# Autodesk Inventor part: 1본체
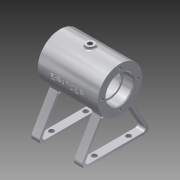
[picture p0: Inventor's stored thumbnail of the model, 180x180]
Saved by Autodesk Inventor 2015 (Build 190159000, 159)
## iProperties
Created: 2016-03
Part Number: 1본체
Material: 알루미늄 6061
Document SubType Name: Modeling
Designer: Administrator
Density: 2.7 g/cm^3
Appearance: 알루미늄 - 평지
Mass: 212.731 g
Surface Area: 333.697 cm^2
Volume: 78.7893 cm^3
Author: Administrator
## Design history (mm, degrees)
sketch "스케치1"
  geometry: C1 r 26 at (0, 0); 1 further point
  constraints: 1 centre point, 1 coincident
  dimensions: "d0" = 52 diameter of C1
extrude "돌출1" new body sketch "스케치1" distance "d1" = 70; taper "d2" = 0 deg
node "작업 평면2"
  node "작업 평면1"
sketch "스케치2"
  geometry: L1 (-33.934, -65)-(33.934, -65); L2 (16.613, -20)-(38.264, -57.5); L3 (-16.613, -20)-(-38.264, -57.5); L4 (14.183, -21.791)-(34.8, -57.5); L5 (-14.183, -21.791)-(-34.8, -57.5); L6 (-32.202, -62)-(32.202, -62); A1 r 26 centre (0, 0) between (16.613, -20) and (-16.613, -20) reference; A2 r 5 centre (-33.934, -60) between (-38.264, -57.5) and (-33.934, -65); A3 r 5 centre (33.934, -60) between (33.934, -65) and (38.264, -57.5); A4 r 3 centre (-32.202, -59) between (-34.8, -57.5) and (-32.202, -62); A5 r 3 centre (32.202, -59) between (32.202, -62) and (34.8, -57.5); 1 further point
  constraints: 12 end point, 12 point on circle, 8 tangent, 4 centre point, 2 equal radius, 2 horizontal
  dimensions: "d5" = 65 distance from line of point (0, 0) L1; "d8" = 5 radius of A2; "d10" = 3 distance between parallel lines of L4 L2; "d11" = 3 distance between parallel lines of L6 L1; "d46" = 3 radius of A4
extrude "돌출2" join sketch "스케치2" distance "d13" = 10; taper "d14" = 0 deg
node "작업 평면3"
sketch "스케치4"
  geometry: L1 (0, 10)-(67.868, 10) reference; L2 (33.934, 10)-(33.934, 37.245); L3 (0, -40)-(67.868, -40) reference; L4 (0, -50)-(67.868, -50) reference; C1 r 3 at (13.934, 5); C2 r 3 at (53.934, 5); C3 r 3 at (13.934, -45); C4 r 3 at (53.934, -45); 1 further point
  constraints: 4 centre point, 2 end point, 1 midpoint, 1 vertical
  dimensions: "d15" = 6 diameter of C1; "d16" = 20 distance from line of L2 C1.centre; "d17" = 5 distance from line of L1 C1.centre; "d18" = 6 diameter of C2; "d19" = 40 distance of C1.centre C2.centre; "d20" = 6 diameter of C3; "d21" = 6 diameter of C4; "d22" = 5 distance from line of L3 C4.centre; "d23" = 40 distance of C3.centre C4.centre; "d24" = 5 distance from line of L4 C3.centre; "d25" = 20 distance from line of C3.centre L2
extrude "돌출3" cut sketch "스케치4" stored distance "d26" = 10; taper "d27" = 0 deg
fillet "모깎기1" dims "d28" = 0.5
sketch "스케치5"
  geometry: L1 (0, 0)-(0, 70); L2 (16, 70)-(0, 70); L3 (0, 0)-(16, 0); L4 (16, 70)-(16, 58.3); L5 (14, 58)-(14, 56); L6 (21, 53)-(21, 17); L7 (16, 0)-(16, 11.7); L8 (14, 12)-(14, 14); L9 (14, 12)-(15.7, 12); L10 (14, 14)-(18, 14); L11 (14, 56)-(18, 56); L12 (14, 58)-(15.7, 58); A1 r 0.3 centre (15.7, 58.3) between (15.7, 58) and (16, 58.3); A2 r 0.3 centre (15.7, 11.7) between (16, 11.7) and (15.7, 12); A3 r 3 centre (18, 17) between (18, 14) and (21, 17); A4 r 3 centre (18, 53) between (21, 53) and (18, 56); 2 further points
  constraints: 24 end point, 8 point on circle, 8 tangent, 5 point on line, 4 centre point, 4 vertical, 3 horizontal, 2 equal radius, 1 perpendicular
  dimensions: "d36" = 42 distance of point (21, 56) point (21, 14); "d40" = 0.3 radius of A1; "d41" = 3 radius of A3
revolve "회전1" sketch "스케치5" stored, may be unused: angle "d42" = 90 deg
chamfer "모따기1" distance "d43" = 1; stored, may be unused: second distance "d44" = 2, angle "d45" = 45 deg
sketch "스케치7"
  geometry: C1 r 17 at (0, 0) reference; 5 further points
  constraints: 1 coincident, 1 vertical alignment, 7 other
  dimensions: "d50" = 360 deg dimension on point (0, 0) point (0, 21) (derived)
hole "구멍1" sketch "스케치7" at (0, 21), (-21, 0), (0, -21), (21, 0) diameter "d52" = 3.242; stored, may be unused: countersink angle "d56" = 90 deg, drill point angle "d58" = 118 deg; dims "d53" = 8, "d54" = 4, "d55" = 2, "d57" = 10
node "작업 평면4"
sketch "스케치8"
  geometry: C1 r 5 at (0, 35); 1 further point
  constraints: 1 centre point
  dimensions: "d59" = 10 diameter of C1; "d60" = 35 distance of point (0, 0) C1.centre
extrude "돌출4" join sketch "스케치8" distance "d61" = 3; taper "d63" = 0 deg; dims "d62" = 5, "d64" = 0
fillet "모깎기2" dims "d65" = 2
sketch "스케치10"
  geometry: C1 r 5 at (0, 0) reference; 2 further points
  constraints: 1 coincident
hole "구멍2" sketch "스케치10" at (0, 0) diameter "d66" = 5.188; stored, may be unused: countersink angle "d70" = 90 deg, drill point angle "d72" = 118 deg; dims "d67" = 12, "d68" = 4, "d69" = 2, "d71" = 16
node "작업 평면5"
sketch "스케치13"
  geometry: L1 (-0.611, 55.739)-(-0.611, 14.261); L2 (-0.611, 14.261)-(0.611, 14.261); L3 (0.611, 14.261)-(0.611, 55.739); L4 (0.611, 55.739)-(-0.611, 55.739); L5 (0.611, 35)-(-19.284, 35); L6 (0, 55.739)-(0, 73.726); L7 (26, 70)-(-26, 70) reference; L8 (26, 0)-(26, 70) reference; 1 further point
  constraints: 4 end point, 2 midpoint, 1 horizontal, 1 vertical, 2 other
  dimensions: "d73" = 35 distance between parallel lines of L7 L5; "d74" = 26 distance between parallel lines of L8 L6
feature "엠보싱1" sketch "스케치13" dims "d1" = 70, "d2" = 0, "d75" = 0.5, "d76" = 0
node "작업 평면6"
sketch "스케치16"
  geometry: L1 (0, 0)-(0, 3) reference; L2 (-31.942, 3)-(0, 3) reference; L3 (-31.942, 0)-(-31.942, 3) reference; L4 (0, 0)-(-31.942, 0) reference; C1 r 6 at (0, 0); 1 further point
  constraints: 1 centre point, 1 coincident
  dimensions: "d83" = 12 diameter of C1
extrude "돌출6" join sketch "스케치16" distance "d84" = 4; taper "d85" = 0 deg
fillet "모깎기3" dims "d86" = 2
sketch "스케치17"
  geometry: C1 r 6 at (0, 0) reference; 2 further points
  constraints: 1 coincident
hole "구멍3" sketch "스케치17" at (0, 0) diameter "d87" = 5.188; stored, may be unused: countersink angle "d91" = 90 deg, drill point angle "d93" = 118 deg; dims "d88" = 12, "d89" = 4, "d90" = 2, "d92" = 16
fillet "모깎기4" dims "d94" = 3
node "솔리드1"
mirror "대칭1"
mirror "대칭2"
node "투영된 루프1"
